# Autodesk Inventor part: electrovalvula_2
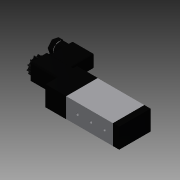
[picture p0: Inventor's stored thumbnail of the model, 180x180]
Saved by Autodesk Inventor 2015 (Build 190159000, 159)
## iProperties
Created: 2016-06
Part Number: electrovalvula_2
Material: Genérico
Document SubType Name: Modeling
Designer: Diego
Density: 1 g/cm^3
Appearance: Valor por defecto
Author: Diego
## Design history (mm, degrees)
sketch "Boceto1"
  geometry: L1 (0, 0)-(52, 0); L2 (52, 0)-(52, 35); L3 (52, 35)-(0, 35); L4 (0, 35)-(0, 0)
  constraints: 8 end point, 2 parallel, 1 horizontal, 1 perpendicular
  dimensions: "d0" = 52 distance of L3.end L2.end; "d1" = 35 distance of L2.end L1.end
extrude "Extrusión1" new body sketch "Boceto1" distance "d2" = 22; taper "d3" = 0 deg
sketch "Boceto2"
  geometry: L1 (0, 0)-(0, 35) reference; L2 (-22, 0)-(-22, 35) reference; L3 (0, 0)-(-22, 0) reference; L4 (0.01, 35.01)-(0.01, -0.01); L5 (0.01, -0.01)-(-22.01, -0.01); L6 (-22.01, -0.01)-(-22.01, 35.01); L7 (-22.01, 35.01)-(0.01, 35.01)
  constraints: 8 end point, 2 other
  dimensions: "d4" = 0.01 distance between parallel lines of L1 L4
extrude "Extrusión2" join sketch "Boceto2" distance "d5" = 7; taper "d6" = 0 deg
sketch "Boceto3"
  geometry: L1 (0, 35)-(0, 0) reference; L2 (0, 0)-(22, 0) reference; L3 (22, 35)-(22, 0) reference; L4 (0, 35)-(22, 35) reference; L5 (22.1, -0.1)-(-0.1, -0.1); L6 (-0.1, -0.1)-(-0.1, 35.1); L7 (-0.1, 35.1)-(22.1, 35.1); L8 (22.1, 35.1)-(22.1, -0.1); 1 further point
  constraints: 8 end point, 3 other
  dimensions: "d7" = 0.1 distance between parallel lines of L3 L8
extrude "Extrusión3" join sketch "Boceto3" distance "d8" = 23; taper "d9" = 0 deg
sketch "Boceto4"
  geometry: L1 (22.1, 35.1)-(-0.1, 35.1) reference; L2 (-0.1, -0.1)-(22.1, -0.1) reference; L3 (22.1, -0.1)-(22.1, 35.1) reference; L4 (22.1, 35.1)-(-0.1, 35.1) reference; L5 (-0.1, 35.1)-(-0.1, -0.1) reference; L6 (20.6, 33.6)-(1.4, 33.6); L7 (1.4, 33.6)-(20.6, 33.6); L8 (20.6, 33.6)-(20.6, 14.4); L9 (20.6, 14.4)-(1.4, 14.4); L10 (1.4, 14.4)-(1.4, 33.6); 1 further point
  constraints: 10 end point, 2 parallel, 1 horizontal, 1 perpendicular
  dimensions: "d12" = 19.2 distance of L7.end L8.end
extrude "Extrusión4" join sketch "Boceto4" distance "d13" = 31; taper "d14" = 0 deg
fillet "Empalme1" dims "d15" = 2
sketch "Boceto5"
  geometry: L1 (0, 15.2)-(-31, 15.2) reference; L2 (-31, 0)-(-6, 0); L3 (-6, 0)-(-6, 15.2); L4 (-6, 15.2)-(-31, 15.2); L5 (-31, 15.2)-(-31, 0); 1 further point
  constraints: 8 end point, 2 parallel, 1 horizontal, 1 perpendicular, 1 point on line
  dimensions: "d16" = 25 distance of L4.end L3.end
extrude "Extrusión5" join sketch "Boceto5" distance "d17" = 3; taper "d18" = 0 deg
sketch "Boceto6"
  geometry: L1 (-31, 0)-(-6, 0) reference; L2 (-31, 0)-(-6, 0) reference; L3 (-6, 0)-(-6, 15.2) reference; L4 (-6, 15.2)-(-31, 15.2) reference; L5 (-31, 15.2)-(-31, 0) reference; L6 (-30.5, 14.7)-(-6.5, 14.7); L7 (-6.5, 14.7)-(-6.5, 0.5); L8 (-6.5, 0.5)-(-30.5, 0.5); L9 (-30.5, 0.5)-(-30.5, 14.7); 1 further point
  constraints: 8 end point, 3 other
  dimensions: "d19" = 0.5 distance between parallel lines of L4 L6
extrude "Extrusión6" join sketch "Boceto6" distance "d20" = 24; taper "d21" = 0 deg
sketch "Boceto7"
  geometry: C1 r 9 at (11, 24); 1 further point
  constraints: 1 centre point
  dimensions: "d22" = 18 diameter of C1
extrude "Extrusión7" join sketch "Boceto7" distance "d23" = 5; taper "d24" = 0 deg
fillet "Empalme2" dims "d25" = 0.5
sketch "Boceto8"
  geometry: C1 r 6.926 at (7.1, -7.417); 1 further point
  constraints: 1 centre point
extrude "Extrusión8" join sketch "Boceto8" distance "d26" = 7; taper "d27" = 0 deg
sketch "Boceto9"
  geometry: C1 r 6.926 at (0, 0) reference; C2 r 6.426 at (0, 0); 1 further point
  constraints: 1 centre point
  dimensions: "d28" = 0.5 radial gap between concentric circles of C1 C2
extrude "Extrusión9" join sketch "Boceto9" distance "d29" = 1; taper "d30" = 0 deg
sketch "Boceto10"
  geometry: L1 (-6.959, 2.593)-(-1.235, 7.323); L2 (-1.235, 7.323)-(5.724, 4.731); L3 (5.724, 4.731)-(7.1, -2.566); L4 (7.1, -16.583)-(7.1, 7.417) reference; L5 (7.1, -2.566)-(1.377, -7.298); L6 (1.377, -7.298)-(-5.631, -4.841); L7 (-5.631, -4.841)-(-6.959, 2.593); 1 further point
  constraints: 12 end point, 1 point on line
  dimensions: "d33" = 7.426 distance of L1.end L2.end; "d34" = 7.426 distance of L2.end L3.end; "d35" = 7.426 distance of L3.end L5.end; "d36" = 7.426 distance of L5.end L6.end
extrude "Extrusión10" join sketch "Boceto10" distance "d37" = 5; taper "d38" = 0 deg
fillet "Empalme3" dims "d39" = 1
sketch "Boceto11"
  geometry: 14 further points
  constraints: 15 other
  dimensions: "d42" = 360 deg dimension on point (0, 0) point (-8.436, 3.136) (derived)
hole "Agujero1" sketch "Boceto11" at (-8.436, 3.136), (-8.874, -1.503), (-6.934, -5.738), (-3.136, -8.436), (1.503, -8.874), (5.738, -6.934), (8.436, -3.136), (8.874, 1.503), (6.934, 5.738), (3.136, 8.436), (-1.503, 8.874), (-5.738, 6.934) diameter "d44" = 4; stored, may be unused: countersink angle "d48" = 90 deg, drill point angle "d50" = 0 deg; dims "d45" = 6, "d46" = 4, "d47" = 2, "d49" = 5
sketch "Boceto12"
  geometry: C1 r 2 at (-18.327, 11.1); 1 further point
  constraints: 1 centre point
  dimensions: "d51" = 4 diameter of C1
extrude "Extrusión11" join sketch "Boceto12" distance "d52" = 5; taper "d53" = 0 deg
sketch "Boceto13"
  geometry: L1 (0, 2.5)-(7.548, 1.47); L2 (18.327, 11.1)-(18.327, -11.1) reference; L3 (0, -2.5)-(7.548, -1.47); A1 r 2.5 centre (0, 0) between (0.67, 2.409) and (0.67, -2.409); A2 r 1.508 centre (7.215, 0) between (7.358, -1.501) and (7.287, 1.506); 1 further point
  constraints: 8 point on circle, 4 end point, 3 point on line, 2 centre point
extrude "Extrusión12" join sketch "Boceto13" distance "d55" = 2; taper "d56" = 0 deg
sketch "Boceto14" dims "d62" = 10
  geometry: L1 (0, 22.01)-(0, -0.01) reference; L2 (0, 11)-(-52, 11); L3 (-52, -0.1)-(-52, 22.1) reference; 4 further points
  constraints: 2 end point, 2 midpoint, 1 horizontal, 1 point on line, 2 other
  dimensions: "d59" = 15 distance of point (-9.657, 11) point (-24.657, 11)
hole "Agujero2" sketch "Boceto14" at (-9.657, 11), (-24.657, 11), (-39.657, 11) diameter "d64" = 3; stored, may be unused: countersink angle "d68" = 90 deg, drill point angle "d70" = 118 deg; dims "d65" = 6, "d66" = 4, "d67" = 2, "d69" = 1
sketch "Boceto15"
  geometry: L1 (0, 22)-(0, 0) reference; L2 (0, 11)-(-52, 11); L3 (-52, 22)-(-52, 0) reference; 2 further points
  constraints: 2 end point, 2 midpoint, 1 point on line
hole "Agujero3" sketch "Boceto15" at (-16.831, 11), (-32.357, 11) diameter "d71" = 3; stored, may be unused: countersink angle "d75" = 90 deg, drill point angle "d77" = 118 deg; dims "d72" = 6, "d73" = 4, "d74" = 2, "d76" = 1
node "Sólido1"
node "Contorno proyectado1"
node "Contorno proyectado2"
node "Contorno proyectado3"
node "Contorno proyectado4"
